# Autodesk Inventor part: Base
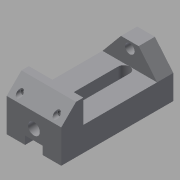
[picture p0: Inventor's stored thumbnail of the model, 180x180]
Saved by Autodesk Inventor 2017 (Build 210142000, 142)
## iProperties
Shininess: 77.0
Length Units: 11269
Angle Units: 11279
Time Units: 11290
Mass Units: 11283
Length Display Precision: 3
Angle Display Precision: 2
Created: 2002-02
Part Number: Base
Document SubType Name: Modeling
Designer: ***
Density: 1 g/cm^3
Material: Generic
Appearance: Default
Density: 0.0
Volumn: 0.0
Area: 0.0
PropertySet Name: Model Information
Control State: 0
Master: False
Checked Out: False
Author: ***
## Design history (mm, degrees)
sketch "Sketch2"
  geometry: L1 (-63.961, -4.254)-(-63.961, -37.254); L2 (-63.961, -37.254)-(88.039, -37.254); L3 (88.039, -37.254)-(88.039, 7.746); L4 (88.039, 7.746)-(68.039, 27.746); L5 (68.039, 27.746)-(58.039, 27.746); L6 (58.039, 27.746)-(58.039, -4.254); L7 (58.039, -4.254)-(-63.961, -4.254)
  constraints: 14 end point, 4 parallel, 1 perpendicular, 1 vertical
  dimensions: "d7" = 10 distance of L4.end L5.end; "d8" = 135 deg angle of L3 L4; "d9" = 33 distance of L1.start L1.end; "d10" = 152 distance of L1.end L2.end; "d11" = 65 distance between parallel lines of L5 L2; "d21" = 30 distance between parallel lines of L3 L6
extrude "Extrusion1" new body sketch "Sketch2" stored distance "d13" = 74; taper "d14" = 0 deg
sketch "Sketch3"
  geometry: L1 (0, 74)-(0, 0) reference; L2 (0, 0)-(-30, 25); L3 (-30, 25)-(-30, 49); L4 (-30, 49)-(0, 74); C1 r 6.5 at (-21, 37)
  constraints: 6 end point, 1 centre point, 1 equal length, 1 parallel
  dimensions: "d15" = 24 distance of L2.end L3.end; "d16" = 30 distance between parallel lines of L3 L1; "d17" = 13 diameter of C1; "d18" = 9 distance from line of L3 C1.centre
extrude "Extrusion2" join sketch "Sketch3" distance "d19" = 22; taper "d20" = 0 deg
sketch "Sketch4"
  geometry: L1 (0, 0)-(0, 74) reference; L2 (0, 0)-(45, 0) reference; C1 r 8 at (25, 37)
  constraints: 1 centre point
  dimensions: "d22" = 16 diameter of C1; "d23" = 25 distance from line of L1 C1.centre; "d24" = 37 distance from line of L2 C1.centre
extrude "Extrusion3" cut sketch "Sketch4" distance "d25" = 13; taper "d26" = 0 deg
sketch "Sketch5"
  geometry: L1 (45, 74)-(0, 74) reference; L2 (65, 0)-(65, 74) reference; 1 further point
  dimensions: "d27" = 12 distance from line of point (51, 62) L1; "d28" = 14 distance from line of L2 point (51, 62)
hole "Hole1" sketch "Sketch5" at (51, 62) diameter "d29" = 4.917; stored, may be unused: countersink angle "d33" = 82 deg, drill point angle "d35" = 0 deg; dims "d30" = 12, "d31" = 8, "d32" = 10, "d34" = 45
mirror "Mirror1"
sketch "Sketch6"
  geometry: L1 (100, 0)-(100, 74) reference; L2 (100, 74)-(0, 74) reference; L3 (14, 45)-(92, 45); L4 (92, 29)-(14, 29); A1 r 8 centre (92, 37) between (92, 29) and (92, 45); A2 r 8 centre (14, 37) between (14, 45) and (14, 29)
  constraints: 4 end point, 4 point on circle, 4 tangent, 2 centre point, 1 horizontal, 1 parallel
  dimensions: "d36" = 8 radius of A2; "d37" = 78 distance of L4.start L4.end; "d38" = 8 distance from line of L1 A1.centre; "d39" = 37 distance from line of L2 A2.centre
extrude "Extrusion4" cut sketch "Sketch6" stored distance "d40" = 13; taper "d41" = 0 deg
sketch "Sketch7"
  geometry: L1 (45, 74)-(0, 74) reference; L2 (11, 49)-(0, 49); L3 (0, 49)-(0, 25); L4 (0, 25)-(11, 25); L5 (11, 25)-(11, 49); L6 (0, 0)-(45, 0) reference; L7 (0, 0)-(0, 74) reference
  constraints: 8 end point, 2 parallel, 1 collinear, 1 horizontal, 1 perpendicular
  dimensions: "d47" = 11 distance of L3.end L4.end; "d48" = 25 distance between parallel lines of L6 L4; "d49" = 24 distance of L2.end L3.end
extrude "Extrusion5" cut sketch "Sketch7" stored distance "d45" = 13; taper "d46" = 0 deg
body "Solid1"
